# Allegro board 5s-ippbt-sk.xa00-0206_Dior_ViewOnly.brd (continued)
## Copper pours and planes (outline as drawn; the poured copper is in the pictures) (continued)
GND on BOTTOM (solid shape): 22.57,4.89 22.57,4.5 22.95,4.12 23.97,4.12 24.6,4.76 25.37,4.76 25.49,4.63 25.49,2.47 25.24,2.22 17.29,2.22 15.74,3.77 15.74,5.17 15.84,5.27 22.19,5.27
GND on BOTTOM (solid shape): 115.03,38.67 115.03,36.25 114.9,36.13 114.62,36.13 113.61,37.14 109.44,37.14 109.31,37.27 109.31,38.77 109.83,39.29 112.73,39.29 112.74,39.3 114.39,39.3
GND on BOTTOM (solid shape): 113.25,30.67 113.25,27.24 111.5,25.49 107.54,25.49 107.26,25.76 107.26,28.63 107.27,28.65 107.27,29.13 107.28,29.14 107.28,31.81 107.41,31.94 111.98,31.94
GND on BOTTOM (solid shape): 46.04,87.93 54.99,87.93 56.1,86.82 56.1,82.21 54.6,80.71 53.1,80.71 51.6,79.21 51.6,75.19 49,72.59 49,69.12 49.04,69.08 49.04,67.47 47.07,65.49 42.65,65.49 41.35,66.8 41.35,89.98 41.67,90.29 43.68,90.29
GND on BOTTOM (solid shape): 84.93,47.09 84.93,46.04 84.17,45.27 82.77,45.27 82.16,45.88 82.16,46.59 82.39,46.82 82.98,46.82 83.03,46.87 83.04,46.88 83.17,46.95 83.24,47.08 83.25,47.09 83.64,47.48 83.65,47.48 83.77,47.56 83.85,47.68 83.85,47.69 83.95,47.79 84.23,47.79
GND on BOTTOM (solid shape): 32.86,20.51 32.86,19.62 32.73,19.49 31.97,19.49 31.84,19.62 31.84,20.05 31.86,20.08 31.89,20.1 32.2,20.28 32.26,20.63 32.27,20.72 32.35,20.76 32.61,20.76
GND on BOTTOM (solid shape): 41.78,14.59 42.35,14.59 42.91,15.15 43.18,15.15 43.25,15.11 43.28,15.03 43.44,14.66 43.84,14.61 43.87,14.62 44.06,14.44 44.06,10.47 43.71,10.12 41.37,10.12 41.01,10.47 41.01,15.05 41.11,15.15 41.22,15.15
GND on BOTTOM (solid shape): 58.73,47.75 58.73,47.75 58.76,47.65 58.82,47.56 58.82,47.56 58.92,47.47 59.02,47.47 59.33,47.16 59.33,46.93 59.62,46.64 59.62,46.22 59.62,46.13 59.46,45.97 57.71,45.97 57.65,46.03 57.65,46.45 57.82,46.61 58.17,46.77 58.23,47.15 58.23,47.61 58.47,47.85 58.63,47.85
GND on BOTTOM (solid shape): 59.69,70.33 59.69,70.26 59.68,70.25 59.68,70.18 59.46,69.96 59.46,69.93 59.45,69.91 59.36,69.78 59.34,69.63 59.1,69.39 58.85,69.31 58.73,69.09 58.72,69.05 58.68,69.04 58.42,69.04 58.33,69.12 58.33,69.63 58.29,69.67 58.29,69.71 58.06,69.93 58.06,70.61 58.28,70.83 59.19,70.83
GND on BOTTOM (solid shape): 78.93,53.36 79.01,53.33 79.11,53.27 79.24,53.24 79.3,53.2 79.33,53.12 79.37,52.93 79.53,52.8 79.56,52.79 79.56,52.44 79.49,52.37 79.49,52.37 79.41,52.32 79.36,52.24 79.36,52.24 79.16,52.04 79.04,52.04 78.36,51.36 78.01,51.36 77.55,51.83 77.55,52.35 78.03,52.84 78.07,52.82 78.36,52.83 78.51,53.08 78.54,53.14 78.6,53.18 78.75,53.22 78.86,53.32
GND on BOTTOM (solid shape): 30.04,52.76 30.04,39.67 28.85,38.49 27.43,38.49 26.09,39.83 24.36,39.83 23.67,39.15 22.6,39.15 22.4,39.35 22.4,39.73 22.14,39.99 16.78,39.99 15.44,41.33 15.44,46.44 16.99,47.99 23.57,47.99 23.8,48.22 25.11,48.22 25.12,48.15 25.13,48.09 25.15,48.03 25.18,47.97 25.21,47.91 25.25,47.86 25.3,47.81 25.35,47.77 25.41,47.74 25.47,47.71 25.53,47.7 25.6,47.69 25.66,47.68 25.73,47.69 25.79,47.7 25.85,47.73 25.91,47.76 25.97,47.79 26.02,47.83 26.06,47.88 26.1,47.94 26.13,47.99 26.16,48.06 26.17,48.12 26.18,48.19 26.18,48.25 26.17,48.32 26.16,48.38 26.13,48.44 26.1,48.5 26.06,48.55 26.02,48.6 25.97,48.65 25.91,48.68 25.85,48.71 25.79,48.73 25.73,48.75 25.66,48.75 25.6,48.75 25.53,48.74 25.47,48.72 25.41,48.7 25.35,48.66 25.3,48.62 25.25,48.58 25.21,48.53 25.18,48.47 25.15,48.41 25.13,48.35 25.12,48.28 25.11,48.22 23.8,48.22 24.6,49.01 24.6,52.48 25.07,52.96 29.84,52.96
GND on BOTTOM (solid shape): 71.91,56.87 71.91,56.79 71.59,56.46 71.39,56.36 71.28,56.17 71.04,55.93 70.77,55.93 70.76,55.94 70.63,56.02 70.49,56.03 70.03,56.03 69.91,56.15 69.9,56.16 69.9,56.16 69.62,56.44 69.62,56.49 69.65,56.54 69.7,56.58 69.75,56.65 69.78,56.72 69.93,56.87 70,56.97 70.17,57.06 70.34,56.97 70.41,56.87 70.53,56.75 70.55,56.69 70.57,56.67 70.75,56.51 70.99,56.47 71.04,56.47 71.06,56.49 71.07,56.5 71.21,56.59 71.3,56.72 71.31,56.74 71.32,56.82 71.37,56.87 71.44,56.87 71.61,57.07 71.71,57.07
GND on BOTTOM (solid shape): outline of 110 points within 27.78,8.82 32.73,14.41
GND on BOTTOM (solid shape): 60.34,65.71 60.34,65.62 60.19,65.49 60.12,65.3 60.1,65.21 60.1,65.11 60.1,65.1 60.09,65.05 60.06,65.04 59.86,64.73 60.1,64.45 60.14,64.43 60.17,64.38 60.12,64.27 60.11,64.15 60.01,64.04 59.93,63.96 59.9,63.92 59.86,63.9 59.82,63.92 59.61,64.06 59.37,63.99 59.36,63.97 59.21,63.97 58.92,63.68 58.91,63.68 58.83,63.68 58.71,63.81 58.71,64.04 58.72,64.05 58.8,64.18 58.8,64.32 58.82,64.41 58.89,64.45 59.11,64.58 59.15,64.83 59.14,64.85 59.22,64.94 59.46,65.05 59.51,65.3 59.53,65.38 59.6,65.42 59.8,65.53 59.86,65.75 59.86,65.77 59.88,65.81 60.01,65.84 60.13,65.92
GND on BOTTOM (solid shape): 73.39,47.05 73.44,46.98 73.45,46.9 73.49,46.82 73.53,46.78 73.6,46.72 73.79,46.53 73.79,45.77 73.6,45.58 73.25,45.58 72.65,44.99 70.72,44.99 70.37,45.34 70.37,46.29 70.54,46.38 70.61,46.57 70.61,46.69 70.62,46.73 70.64,46.73 70.98,46.73 71.13,47.04 71.18,47.07 71.23,47.07 71.3,47.06 71.37,47.07 71.42,47.07 71.47,47.04 71.62,46.73 71.96,46.73 71.98,46.73 71.99,46.69 71.99,46.57 72.27,46.29 72.55,46.57 72.55,46.69 72.56,46.73 72.58,46.73 72.93,46.73 73.07,47.04 73.12,47.07 73.17,47.07 73.24,47.06 73.31,47.07
GND on BOTTOM (solid shape): 85.54,70.93 85.54,68.23 84.9,67.59 84.54,67.59 84.45,67.64 84.44,67.74 84.16,68.23 83.76,67.82 83.64,67.7 83.35,67.7 83.3,67.75 83.25,67.8 83.23,67.81 83.22,67.87 83.22,67.88 83.25,67.97 83.24,68.06 83.36,68.18 83.78,68.26 83.77,68.68 83.74,68.76 83.77,68.82 83.8,69.27 83.36,69.34 83.32,69.31 83.19,69.45 83.21,69.48 83.14,69.92 82.7,69.9 82.63,69.87 82.56,69.89 82.38,69.98 82.19,69.95 82.08,70.06 81.93,70.1 81.81,70.1 81.79,70.09 81.75,70.09 81.71,70.09 81.68,70.1 81.58,70.1 81.58,70.29 82.08,70.79 83.95,70.79 83.95,70.8 84.52,71.36 85.1,71.36
GND on BOTTOM (solid shape): 83,66.27 83,66.08 82.91,65.98 82.9,65.98 82.78,65.87 82.74,65.72 82.74,65.48 82.32,65.06 82.32,65.05 82.22,64.97 82.18,64.92 82.1,64.88 82.02,64.92 81.79,65.06 81.55,64.97 81.54,64.96 81.28,64.96 81.26,64.97 81.01,65.05 80.78,64.9 80.7,64.85 80.61,64.9 80.54,64.98 80.44,65.04 80.39,65.09 80.39,65.17 80.41,65.42 80.29,65.63 80.24,65.67 80.2,65.71 80.18,65.75 80.19,65.8 80.27,65.85 80.34,65.91 80.35,65.93 80.59,65.93 80.75,65.77 80.96,65.45 81.32,65.59 81.41,65.65 81.49,65.6 81.82,65.44 82.07,65.71 82.08,65.75 82.12,65.77 82.39,65.93 82.46,66.25 82.64,66.43 82.84,66.43
GND on BOTTOM (solid shape): 76.91,50.25 76.96,50.3 77.03,50.31 77.15,50.29 77.28,50.31 77.31,50.31 77.34,50.28 77.39,50.19 77.48,50.12 77.53,50.03 77.48,49.94 77.47,49.93 77.32,49.67 77.48,49.41 77.53,49.32 77.48,49.23 77.45,49.21 77.35,49.1 77.32,48.97 77.33,48.88 77.35,48.84 77.37,48.8 77.39,48.76 77.42,48.69 77.39,48.63 77.15,48.39 76.92,48.36 76.75,48.2 76.73,48.18 76.48,48.18 76.47,48.19 76.38,48.26 76.28,48.3 76.19,48.32 75.99,48.31 75.95,48.45 75.85,48.55 75.8,48.63 75.84,48.71 75.92,48.79 75.96,48.9 76,48.92 76.02,48.91 76.12,48.9 76.23,48.91 76.3,48.91 76.35,48.85 76.84,48.73 76.78,49.23 76.73,49.32 76.78,49.41 76.94,49.67 76.78,49.94 76.73,50.03 76.88,50.2 76.9,50.23
GND on BOTTOM (solid shape): 79.73,69.3 80,69.15 80.26,69.3 80.35,69.3 80.55,69.1 80.55,69.08 80.58,69.01 80.62,68.94 80.7,68.87 80.8,68.83 80.82,68.83 81.22,68.43 81.69,67.95 81.81,67.95 82.38,67.37 82.38,67.09 82.29,67 82,67 81.99,67 81.85,67.04 81.71,67 81.7,67 81.29,67 81.27,67 81.12,67.04 80.97,66.99 80.91,66.94 80.87,66.88 80.78,66.83 80.69,66.88 80.45,67.04 80.19,66.93 80.15,66.86 79.75,66.86 79.68,66.89 79.62,66.9 79.6,66.9 79.51,66.99 79.5,67.02 79.5,67.26 79.58,67.38 79.61,67.52 79.61,67.53 79.63,67.57 79.76,67.62 79.81,67.61 79.85,67.59 80.3,67.47 80.56,67.86 80.54,67.99 80.46,68.12 80.44,68.18 80.46,68.25 80.44,68.8 79.88,68.82 79.85,68.8 79.82,68.82 79.58,68.9 79.36,68.78 79.31,68.78 79.2,68.67 79.17,68.67 78.94,68.6 78.79,68.42 78.78,68.39 78.52,68.39 78.46,68.45 78.46,68.74 78.56,68.84 78.75,68.84 79.11,69.2 79.12,69.21 79.21,69.24 79.29,69.3
GND on BOTTOM (solid shape): outline of 248 points within 5.5,4.95 13.5,12.95
GND on BOTTOM (solid shape): outline of 248 points within 5.5,110.95 13.5,118.95
GND on BOTTOM (solid shape): outline of 248 points within 110.5,110.95 118.5,118.95
GND on BOTTOM (solid shape): outline of 248 points within 110.5,4.95 118.5,12.95
GND on BOTTOM (solid shape): outline of 115 points within 75.97,64.85 79.53,69.3
GND on BOTTOM (solid shape): outline of 142 points within 72.5,61.83 75.56,68.91
GND on BOTTOM (solid shape): outline of 2749 points within 73.96,53.11 85.01,65.8
GND on BOTTOM (solid shape): outline of 4388 points within 0.51,0.51 123.49,121.99
GND on BOTTOM (solid shape): outline of 5719 points within 57.62,45.68 75.89,73.11
GND on VCC (solid shape): outline of 3194 points within 0.51,0.51 123.49,122.79
GND on IN1 (solid shape): outline of 1232 points within 13.56,103.31 28.29,120.7
GND on IN1 (solid shape): outline of 325 points within 0.51,0.51 123.49,121.99
GND on IN2 (solid shape): outline of 324 points within 0.51,0.51 123.49,121.99
GND on GND (solid shape): outline of 3194 points within 0.51,0.51 123.49,122.79
+1P0V on TOP (solid shape): outline of 345 points within 56.33,34.13 69.13,40.19
+1P0VSB on BOTTOM (solid shape): 75.44,61.77 75.52,61.8 75.59,61.76 75.84,61.64 76.1,61.76 76.17,61.8 76.25,61.77 76.38,61.63 76.38,61.46 76.26,61.34 76.18,61.31 76.11,61.35 75.78,61.48 75.54,61.22 75.52,61.19 75.48,61.17 75.47,61.17 75.31,61.14 75.18,61.05 75.15,61.02 75.1,61.05 75.06,61.06 75.01,61.09 74.98,61.14 74.96,61.21 74.82,61.35 74.71,61.35 74.63,61.37 74.56,61.41 74.48,61.49 74.4,61.49 74.4,61.63 74.49,61.63 74.49,61.63 75.3,61.63
+1P0VSB on BOTTOM (solid shape): 81.65,69.9 81.75,69.88 81.84,69.9 81.93,69.9 82.01,69.85 82.03,69.76 82.15,69.37 82.56,69.4 82.57,69.41 82.72,69.41 82.73,69.4 82.86,69.34 83.01,69.34 83.17,69.18 83.17,69.03 82.88,68.74 82.79,68.71 82.72,68.75 82.31,68.85 82.19,68.45 82.19,68.42 82.17,68.39 82.11,68.32 82.06,68.24 82.05,68.24 82.02,68.21 81.84,68.21 81.65,68.4 81.65,68.47 81.66,68.48 81.72,68.68 81.64,68.87 81.77,69.29 81.45,69.58 81.46,69.63 81.46,69.67 81.58,69.8 81.58,69.85 81.63,69.9
+1P05V on TOP (solid shape): 66.24,39.84 66.24,38.52 66.06,38.34 65.5,38.34 65.24,38.59 65.24,39.84 65.35,39.94 66.13,39.94
+1P5V on BOTTOM (solid shape): 36.29,21.4 36.29,19.62 36.16,19.49 35.91,19.49 35.65,19.74 34.26,19.74 34.13,19.87 34.13,20.76 33.62,21.27 33.49,21.27 33.37,21.4 33.37,21.78 35.91,21.78
+1P05V on BOTTOM (solid shape): 66.39,39.07 66.39,38.72 67.3,37.8 67.68,37.8 67.94,37.55 67.96,37.55 68.14,37.37 68.15,37.37 68.28,37.29 68.43,37.27 68.58,37.3 68.7,37.37 69.31,37.37 69.5,37.18 69.5,34.24 69.26,33.99 68.52,33.99 68.22,34.3 66.72,34.3 66.59,34.43 66.59,34.83 66.69,34.93 67.86,34.93 68.29,35.37 68.29,36.23 68.14,36.38 66.92,36.38 65.4,37.91 65.4,39.1 65.65,39.35 66.11,39.35
+1P05V on BOTTOM (solid shape): outline of 114 points within 67.31,57.1 68.93,62.91
+1P05V on IN1 (solid shape): 67.96,62.59 68.14,62.42 68.14,62.06 68.1,61.98 68.01,61.96 67.49,61.57 68.01,61.18 68.1,61.16 68.14,61.08 68.14,59.93 67.83,59.62 67.76,59.61 67.24,59.61 66.88,59.96 66.88,62.11 67.37,62.59 67.96,62.59
+1P35V on TOP (solid shape): 62.12,44.21 62.12,41.84 61.99,41.72 59.02,41.72 58.89,41.84 58.89,44.13 59.02,44.26 62.07,44.26
+1P35V on BOTTOM (solid shape): 62.12,43.27 62.12,38.29 61.99,38.16 59.96,38.16 59.45,38.67 57.17,38.67 56.79,39.05 56.79,39.91 57.1,40.23 58.06,40.23 58.65,40.16 58.68,40.75 58.67,40.79 58.68,40.82 58.77,40.97 58.79,41.13 58.79,43.38 58.89,43.48 61.9,43.48
+1P35V on IN2 (solid shape): outline of 1417 points within 57.83,41.33 69.57,61.93
+1P35V_DUAL on TOP (solid shape): outline of 9156 points within 21.56,33.18 66.7,89.37
+1P35V_DUAL on BOTTOM (solid shape): 55.34,41.59 55.34,40.32 55.21,40.19 54.2,40.19 54.14,40.24 54.15,40.27 54.16,40.48 54.07,40.67 54.07,41.46 54.58,41.97 54.96,41.97
+1P35V_DUAL on BOTTOM (solid shape): 22.45,77.78 22.45,76.89 21.61,76.05 15.26,76.05 14.39,76.92 13.8,76.92 13.78,76.95 13.78,77.07 13.81,77.1 14.23,77.1 14.25,77.08 15.4,77.08 15.44,77.05 17.11,77.05 18.1,78.04 22.19,78.04
+1P35V_DUAL_BOOT_C on BOTTOM (solid shape): 16.83,77.81 16.83,77.38 16.75,77.29 15.4,77.29 15.39,77.3 14.28,77.3 14.26,77.31 13.8,77.31 13.78,77.33 13.78,77.48 13.8,77.5 14.31,77.5 14.34,77.53 15.04,77.53 15.45,77.94 16.71,77.94
+1P35V_DUAL_HG_D on TOP (solid shape): 16.73,81.21 16.73,79.82 16.6,79.69 15.71,79.69 15.46,79.94 15.46,80.32 15.08,80.7 14.44,80.7 14.32,80.83 14.32,81.21 14.44,81.34 16.6,81.34
+1P35V_DUAL_HG_D on BOTTOM (solid shape): 15.13,78.47 15.13,78.04 14.83,77.73 14.24,77.73 14.22,77.71 13.8,77.71 13.78,77.73 13.78,77.86 13.8,77.89 14.24,77.89 14.45,78.1 14.45,78.4 14.7,78.65 14.95,78.65
+1P35V_DUAL_LG_D on TOP (solid shape): 14.7,91.75 14.7,91.37 14.57,91.25 11.87,91.25 11.78,91.33 11.78,91.75 11.9,91.88 14.57,91.88
+1P35V_DUAL_PHASE_D on TOP (solid shape): 20.29,88.96 20.29,82.86 19.23,81.81 17,81.81 16.78,81.59 14.57,81.59 14.32,81.85 14.32,83.37 14.95,84.01 14.95,88.06 15,88.11 15,89.25 14.95,89.3 14.95,91.37 15.21,91.63 17.62,91.63
+1P35V_DUAL_SN_C on TOP (solid shape): 14.09,85.63 14.09,84.39 13.71,84.01 12.67,84.01 12.54,84.13 12.54,86.29 12.67,86.42 13.3,86.42
+1P35V_DUAL_VIN on TOP (solid shape): 12.67,83.12 12.94,83.12 13.17,83.04 13.41,83.12 13.81,83.12 13.94,82.99 13.94,80.83 9.75,80.83 7.71,82.86 7.71,85.4 7.97,85.66 10.13,85.66
+1P35V_DUAL_VIN on BOTTOM (solid shape): 11.78,84.01 11.78,82.99 11.65,82.86 9.44,82.86 8.81,82.23 8.22,82.23 7.89,82.56 6.65,82.56 6.44,82.76 6.44,85.53 6.57,85.66 10.13,85.66
+3P3V on TOP (solid shape): 31.34,22.54 31.34,19.11 32.1,18.35 33.42,18.35 34.17,17.6 34.17,16.1 34,15.93 30.7,15.93 29.43,17.2 29.43,22.54 29.94,23.05 30.83,23.05
+3P3V on TOP (solid shape): 85.87,8.72 85.87,7.88 85.51,7.53 83.53,7.53 83.3,7.3 83.3,6.82 83.18,6.69 82.54,6.69 82.35,6.88 82.35,8.38 83.13,9.15 83.76,9.15 83.81,9.2 85.39,9.2
+3P3V on TOP (solid shape): 115.13,37.58 115.13,37.32 115.08,37.27 113.58,37.27 113.56,37.25 113.56,37.09 113.58,37.07 115.08,37.07 115.13,37.02 115.13,36.81 115.08,36.76 113.5,36.76 112.97,36.23 111.45,36.23 111.14,36.53 111.14,37.58 111.27,37.7 115,37.7
+3P3V on TOP (solid shape): 115.13,20.48 115.13,20.3 115.11,20.28 113.61,20.28 113.58,20.25 113.58,20.08 113.61,20.05 115.11,20.05 115.13,20.02 115.13,19.8 115.11,19.77 113.61,19.77 113.58,19.74 113.58,19.59 113.61,19.57 115.08,19.57 115.13,19.52 115.13,19.31 115.08,19.26 113.52,19.26 113.48,19.26 113,19.26 112.98,19.25 111.1,19.25 110.58,18.73 110.58,16.32 110.6,16.3 110.3,16.01 108.88,16.01 108.45,16.44 108.45,17.69 108.84,18.08 108.84,19.28 110.1,20.53 115.08,20.53
+3P3V on BOTTOM (solid shape): 31.46,22.28 31.46,19.87 31.34,19.74 29.94,19.74 29.81,19.87 29.81,22.28 30.19,22.67 31.08,22.67
+3P3V on BOTTOM (solid shape): 110.71,19.69 110.71,15.93 110.46,15.68 108.55,15.68 108.3,15.93 108.3,17.54 108.91,18.14 108.91,19.8 109.24,20.13 110.28,20.13
+3P3V on BOTTOM (solid shape): 6.81,67.4 6.81,66.88 6.4,66.47 5.09,66.47 4.46,65.84 4.46,62.86 4.11,62.51 3.52,62.51 3.17,62.86 3.17,67.07 3.84,67.74 6.47,67.74
+3P3V on BOTTOM (solid shape): outline of 454 points within 82.26,4.28 94.94,11.06
+3P3V on IN1 (solid shape): 83.43,8.7 83.43,7.15 83.08,6.79 82.03,6.79 81.55,7.27 81.55,9.48 82.64,9.48
+3P3V on IN1 (solid shape): 95.83,9.15 95.83,8.19 95.39,7.76 94.35,7.76 94,8.11 94,9.74 95.24,9.74
+3P3V on IN1 (solid shape): 35.91,16.57 35.91,15.17 35.65,14.92 31.34,14.92 31.21,15.05 31.21,16.57 31.46,16.82 35.65,16.82
+3P3V on IN1 (solid shape): 110.72,17.55 110.72,16.07 110.48,15.83 107.21,15.83 106.37,16.67 106.37,17.28 107.05,17.97 110.3,17.97
+3P3VSB on TOP (solid shape): 21.8,96.53 21.8,94.42 21.65,94.27 19.54,94.27 19.18,94.62 19.18,96.5 19.69,97.01 21.32,97.01
+3P3VSB on TOP (solid shape): 45.59,93.71 45.59,92.8 45.08,92.29 43.86,92.29 43.27,92.87 43.27,94.78 43.5,95.01 44.29,95.01
+3P3VSB on TOP (solid shape): 62.76,95.08 62.76,94.62 62.31,94.17 62.31,93.38 62.13,93.2 60.45,93.2 59.94,92.69 58.41,92.69 58.21,92.89 58.21,94.19 58.29,94.26 59.7,94.26 60.67,95.24 62.6,95.24
+3P3VSB on TOP (solid shape): outline of 193 points within 30.8,91.22 36.06,94.42
+3P3VSB on BOTTOM (solid shape): 25.67,12.25 25.67,11.36 25.21,10.91 23.28,10.91 23.08,11.11 23.08,12.43 23.31,12.66 25.27,12.66
+3P3VSB on BOTTOM (solid shape): outline of 226 points within 29.15,2.98 40.61,19.36
+3P3VSB on IN1 (solid shape): 5.94,71.57 5.94,68.85 5.81,68.72 4.05,68.72 3.85,68.91 3.85,71.51 4.2,71.86 5.65,71.86
+3P3VSB on IN1 (solid shape): 7.24,92.04 7.24,89.32 7.1,89.19 5.34,89.19 5.14,89.39 5.14,91.98 5.5,92.34 6.95,92.34
+3P3VSB on IN2 (solid shape): 5.91,71.41 5.91,69.5 5.63,69.22 4.11,69.22 3.8,69.53 3.8,71.28 4.23,71.71 5.61,71.71
+3P3VSB on IN2 (solid shape): 7.51,93.1 7.51,91.55 7.21,91.25 5.3,91.25 5.02,91.53 5.02,93.05 5.33,93.35 7.26,93.35
+3P3VSB on IN2 (solid shape): 21.58,96.45 21.58,94.9 21.28,94.6 19.37,94.6 19.09,94.88 19.09,96.4 19.4,96.71 21.33,96.71
+3P3VSB on IN2 (solid shape): 24.35,11.87 24.35,10.47 23.61,9.74 22.65,9.74 22.19,10.19 22.19,12.12 22.45,12.38 23.84,12.38
+3P3VSB on IN2 (solid shape): 62.83,95.03 62.83,94.47 61.26,92.9 59.45,92.9 59.05,93.3 59.05,93.91 60.47,95.34 62.53,95.34
+3P3VSB on IN2 (solid shape): outline of 398 points within 44.49,91.55 55.24,97.21
+3P3VSB_HG_D on BOTTOM (solid shape): 29.1,10.9 29.1,10.51 29.02,10.43 27.35,10.43 27.18,10.25 27.18,9.87 27.01,9.71 26.64,9.71 26.51,9.84 26.51,10.07 25.93,10.65 25.93,11.23 25.94,11.25 28.75,11.25
+3P3VSB_LG_D on BOTTOM (solid shape): 25.49,1.71 25.49,1.46 25.37,1.33 22.19,1.33 22.06,1.46 22.06,1.71 22.19,1.84 25.37,1.84
+3P3VSB_LG_D on BOTTOM (solid shape): 12.06,31.16 11.78,30.87 11.3,30.87 11.19,30.97 11.19,31.84 11.5,32.14 12.06,32.14
+3P3VSB_PHASE_D on BOTTOM (solid shape): 28.92,10.01 28.92,8.82 30.57,7.17 30.57,1.84 30.19,1.46 26,1.46 25.84,1.62 25.84,7.13 26.51,7.81 26.51,9.08 26.76,9.33 27.03,9.33 27.54,9.84 27.54,10 27.62,10.08 28.85,10.08
+3P3VSB_SN_D on BOTTOM (solid shape): 23.84,6.92 23.84,4.5 23.72,4.38 23.08,4.38 22.95,4.5 22.95,5.14 22.12,5.98 22.12,6.33 22.32,6.54 22.57,6.54 23.08,7.04 23.72,7.04
+V_AXG_HG_D on BOTTOM (solid shape): 103.09,37.78 103.09,36.89 102.96,36.76 99.79,36.76 99.66,36.89 99.66,37.65 100.17,38.16 102.71,38.16
+V_AXG_HG_D on BOTTOM (solid shape): 103.19,57.97 103.19,57.69 102.96,57.46 102.63,57.46 102.11,57.99 102.11,58.46 102.71,58.46
+V_AXG_LGATE_D on BOTTOM (solid shape): 111.68,25.18 111.68,23.73 111.45,23.5 111.02,23.5 110.29,24.23 109.28,24.23 109.19,24.32 107.41,24.32 107.28,24.44 107.28,24.95 107.41,25.08 108.81,25.08 108.96,25.23 111.63,25.23
+V_AXG_PHASE on BOTTOM (solid shape): 101.44,36.25 103.22,36.25 103.47,36 103.47,30.92 104.61,29.78 105.91,29.78 106.67,30.54 106.9,30.54 107.03,30.41 107.03,29.65 106.39,29.02 106.39,24.67 105.83,24.11 96.18,24.11 95.85,24.44 95.85,27.11 95.98,27.24 98.19,27.24 98.43,27.48 98.43,28.8 99.6,29.97 99.6,36.32 99.66,36.38 101.31,36.38
+V_AXG_SN on BOTTOM (solid shape): 106.77,30.95 105.99,30.16 104.87,30.16 104.74,30.29 104.74,31.68 104.87,31.81 106.77,31.81
+VCORE on TOP (solid shape): outline of 458 points within 68.5,58.95 97.22,87.18
+VCORE on BOTTOM (solid shape): outline of 118 points within 71.72,79.13 97.76,85.91
+VCORE on BOTTOM (solid shape): outline of 145 points within 69.6,56.68 72.64,64.27
+VCORE on IN1 (solid shape): outline of 1497 points within 64.48,56.66 74.34,82.71
+VCORE on IN2 (solid shape): outline of 2546 points within 66.92,56.64 77.16,85.38
+VCORE_+19V on BOTTOM (solid shape): 116.55,97.67 116.55,92.92 116.54,92.91 116.54,92.25 115.92,91.63 108.04,91.63 107.31,90.89 107.31,90 107.03,89.72 103.42,89.72 102.86,90.28 102.86,93.46 104.06,94.65 111.69,94.65 111.69,94.65 111.86,94.65 112.11,94.9 112.11,97.59 112.49,97.98 116.25,97.98
+VCORE_HG_D on BOTTOM (solid shape): 101.82,93.91 101.82,93.4 101.69,93.28 98.39,93.28 98.26,93.4 98.26,94.67 98.39,94.8 100.93,94.8
+VCORE_LGATE_D on BOTTOM (solid shape): 109.69,81.59 109.69,80.2 109.44,79.94 106.77,79.94 106.16,80.55 106.16,81.49 106.27,81.59 108.02,81.59 108.17,81.75 109.54,81.75
+VCORE_PHASE on BOTTOM (solid shape): 102.07,92.77 102.07,89.72 102.58,89.21 105.25,89.21 105.76,88.71 105.76,87.94 105.63,87.82 105.5,87.82 105.38,87.94 105.38,88.2 105,88.58 102.96,88.58 102.74,88.35 102.74,87.44 102.74,87.39 102.74,86.57 103.12,86.19 105.66,86.19 105.76,86.09 105.76,85.51 105.58,85.33 105.58,81.11 105.22,80.76 100.65,80.76 100.47,80.93 100.47,84.01 98.01,86.47 95.47,86.47 94.99,86.95 94.99,89.09 95.37,89.47 97.12,89.47 98.52,90.86 98.52,92.82 98.65,92.95 101.9,92.95
+VCORE_SN on BOTTOM (solid shape): 105.02,87.26 105.63,87.26 105.68,87.21 105.68,86.62 105.55,86.5 103.47,86.5 102.99,86.98 102.99,87.89 103.29,88.2 104.08,88.2
+VNN on TOP (solid shape): 73.4,60.99 73.4,59.98 73.52,59.86 73.52,56.05 72.55,55.08 69.29,55.08 69.07,55.3 69.07,56.12 69.33,56.38 71.81,56.38 71.94,56.51 72.07,56.51 72.23,56.67 72.23,57.16 72.07,57.32 71.78,57.32 71.49,57.62 71.5,57.72 71.64,57.9 71.67,58.02 71.97,58.14 72.09,58.45 72.23,58.6 72.71,58.6 72.81,58.71 72.81,59.67 72.75,59.73 72.6,59.73 72.58,59.75 72.41,59.75 72.25,59.91 72.25,60.91 72.43,61.1 73.3,61.1
+VNN on TOP (solid shape): outline of 487 points within 72.23,28.38 99.37,40.04
+VNN on BOTTOM (solid shape): 77.39,36.94 79.16,36.94 79.47,36.64 79.47,35.37 79.15,35.05 79,34.95 78.9,34.79 78.71,34.6 78.71,33.33 78.52,33.14 72.8,33.14 72.74,33.21 72.74,37.52 72.99,37.78 76.55,37.78
+VNN on BOTTOM (solid shape): 98.58,39.49 99.27,39.49 99.51,39.25 99.51,38.06 99.1,37.65 99.1,30.92 98.7,30.51 94.43,30.51 94,30.95 93.36,30.95 92.8,31.51 92.8,33.21 91.91,34.1 90.77,34.1 90.48,34.39 90.48,36.59 91.33,37.44 91.33,38.08 92.75,39.51 98.57,39.51
+VNN on BOTTOM (solid shape): outline of 127 points within 68.87,54.71 73.8,60.56
+VNN on IN1 (solid shape): outline of 2457 points within 65.63,36.06 79.39,60.22
+VNN on IN2 (solid shape): outline of 3510 points within 65.27,31.56 78.61,60.26
+VNN_+19V on BOTTOM (solid shape): 109.03,37.25 109.03,36.43 109.36,36.1 109.44,36.1 109.54,36 114.24,36 114.85,35.39 114.85,31.81 114.39,31.35 113.86,31.35 112.67,32.55 104.44,32.55 104.01,32.98 104.01,37.32 104.36,37.68 108.6,37.68
+VTT_DDR on TOP (solid shape): 36.67,31.02 38.3,31.02 38.46,30.86 38.46,30.2 38.37,30.11 35.4,30.11 34.66,29.37 33.62,29.37 32.81,30.18 30.62,30.18 30.29,30.51 30.29,31.58 30.4,31.68 36.01,31.68
+VTT_DDR on BOTTOM (solid shape): 15.59,75.4 15.59,71.56 15.46,71.43 12.84,71.43 12.29,71.99 12.29,72.53 12.39,72.63 13.67,72.63 14.63,73.09 14.47,74.15 14.44,74.17 14.44,74.33 14.57,74.62 14.44,74.92 14.44,74.96 14.44,74.96 14.44,75.11 13.78,75.78 13.78,76.67 13.81,76.69 14.29,76.69
CARD_3V3 on TOP (solid shape): outline of 195 points within 7.56,59.65 11.42,67.42
CARD_3V3 on BOTTOM (solid shape): 9.64,69.2 9.64,65.26 9.44,65.06 7.97,65.06 7.51,65.52 7.51,67.04 5.96,68.59 5.96,69.22 6.47,69.73 9.11,69.73
CARD_3V3 on BOTTOM (solid shape): 9.61,60.95 9.61,60.76 9.52,60.66 9.52,59.95 9.49,59.93 9.49,59.09 9.44,59.04 9.29,59.04 9.24,59.09 9.24,59.75 8.65,60.33 8.65,60.69 9.07,61.11 9.46,61.11
CARD_3V3_F on TOP (solid shape): 14.96,63.64 15.03,63.55 15.13,63.49 15.49,63.13 17.09,63.13 17.29,62.92 17.29,62.26 17.16,62.14 15.28,62.14 14.57,62.85 14.57,63.46 14.75,63.64
CARD_3V3_F on BOTTOM (solid shape): 13.05,69.53 13.05,68.91 12.79,68.65 12.36,68.65 12.36,68.65 11.91,68.46 11.97,67.97 12,67.9 11.96,67.82 11.84,67.37 12.22,67.1 12.3,67.1 12.45,66.95 14.16,66.95 14.66,66.45 14.66,65.9 14.41,65.57 14.5,65.17 14.5,64.13 14.94,63.68 14.94,63.68 15.09,63.51 15.3,63.44 15.32,63.44 15.55,63.22 15.55,62.8 15.38,62.63 14.53,62.63 14.37,62.8 13.51,62.8 13.3,63 13.3,65.08 13.05,65.34 12.69,65.34 12.6,65.38 12.6,65.48 12.22,66.05 11.85,65.48 11.84,65.38 11.76,65.34 10.51,65.34 10.13,65.72 10.13,69.53 10.37,69.77 12.81,69.77
DRAM_V1P0_S0IX on TOP (solid shape): 67.64,42.37 67.64,41.96 67.76,41.84 67.76,40.88 67.66,40.78 66.74,40.78 66.65,40.87 66.65,41.65 66.74,41.74 66.74,42.36 66.72,42.39 66.72,42.49 66.83,42.59 67.42,42.59
DRAM_V1P0_S0IX on TOP (solid shape): 68.14,57.81 68.14,57.48 67.98,57.32 67.62,57.32 67.53,57.23 67.53,53.73 67.43,53.63 66.97,53.63 66.84,53.76 66.84,57.82 66.96,57.94 68.01,57.94
DRAM_V1P0_S0IX on BOTTOM (solid shape): outline of 96 points within 66.58,55.57 67.67,61.33
LAN_REGOUT on BOTTOM (solid shape): 55.62,95.18 57.43,95.18 57.44,95.17 57.56,95.17 57.65,95.08 57.65,93.43 57.6,93.38 56,93.38 54.65,94.73 54.65,95.48 54.72,95.54 55.26,95.54
LAN_REGOUT_R on TOP (solid shape): outline of 178 points within 49.83,93.53 59.78,100.26
LAN_REGOUT_R on BOTTOM (solid shape): 59.66,95.31 59.66,93.28 58.54,92.16 58.31,92.16 58.08,92.39 58.08,92.82 58.18,92.92 58.49,92.92 58.64,93.07 58.64,94.65 58.68,94.65 58.68,94.71 59.4,95.44 59.53,95.44
PCIE_V1P0_S3 on BOTTOM (solid shape): 76.15,55.53 76.29,55.53 76.43,55.38 76.43,55.22 76.24,55.03 76.24,54.28 75.96,54 75.94,53.97 75.91,53.96 74.25,53.96 74.12,54.09 74.12,54.92 74.27,55.06 74.38,55.06 74.51,54.95 74.66,54.89 74.81,54.74 74.87,54.67 74.95,54.61 75.19,54.59 75.37,54.74 75.44,54.81 75.59,54.81 75.91,55.13 75.91,55.48 75.86,55.53 75.84,55.53 75.71,55.66 75.71,55.71 75.79,55.79 75.89,55.79
RING2 on TOP (solid shape): 11.88,105.55 11.88,105.04 12.06,104.86 12.06,104.58 11.77,104.29 11.69,104.23 11.6,104.12 11.17,104.12 10.98,104.31 10.98,104.8 11.27,105.09 11.27,105.44 11.42,105.6 11.83,105.6
RING2 on BOTTOM (solid shape): outline of 184 points within 10.66,103.51 20.21,106.79
RING2_B on TOP (solid shape): 22.42,107.83 22.42,106.33 22.17,106.08 20.74,106.08 19.96,106.87 19.96,107.98 20.08,108.11 22.14,108.11
RING2_B on BOTTOM (solid shape): 22.5,107.48 22.5,106.88 22.61,106.77 23.39,106.77 23.64,106.51 24.03,106.51 24.26,106.39 24.51,106.43 24.54,106.45 24.73,106.26 24.73,105.8 24.65,105.72 23.69,105.72 23.44,105.98 22.17,105.98 22.04,105.85 21.15,105.85 20.92,106.08 20.92,106.82 20.97,106.87 21.46,106.87 21.68,107.1 21.68,107.13 21.69,107.13 21.69,107.49 21.91,107.71 22.27,107.71
SLEEVE on TOP (solid shape): 11.85,106.38 11.85,105.95 11.8,105.9 11.24,105.9 11.02,105.67 11.02,105.19 10.86,105.04 10.51,105.04 10.43,105.11 10.43,106.31 10.61,106.49 11.75,106.49
SLEEVE on BOTTOM (solid shape): outline of 144 points within 6.6,104.43 20.19,109.13
SLEEVE_B on BOTTOM (solid shape): 23.53,111.85 23.54,111.84 23.78,111.43 24.19,111.18 24.21,111.18 24.71,110.68 24.71,109.54 24.53,109.2 24.71,108.87 24.71,107.45 24.66,107.4 24.05,107.4 23.87,107.58 23.76,107.58 23.75,107.58 23.6,107.62 23.45,107.59 23.45,107.59 22.67,107.59 22.35,107.91 21.83,107.91 21.49,107.57 21.49,107.37 21.44,107.32 21,107.32 20.85,107.48 20.85,108.26 20.19,108.92 20.19,109.38 20.85,110.04 20.85,111.46 21.28,111.9 23.49,111.9
UNCORE_V1P0_S0IX on BOTTOM (solid shape): 73.27,61.86 73.27,61.85 73.36,61.72 73.51,61.64 73.98,61.17 73.98,61.02 74.07,60.96 74.13,60.9 74.15,60.83 74.11,60.66 73.95,60.59 73.89,60.58 73.84,60.57 73.8,60.61 73.57,60.7 73.35,60.61 73.22,60.61 72.77,61.06 72.73,61.09 72.71,61.12 72.71,61.25 72.74,61.28 72.77,61.31 72.84,61.62 72.67,61.89 72.65,61.92 72.65,61.96 72.83,62.14 73,62.14
USB_V1P0_S3 on BOTTOM (solid shape): 76.08,63.57 76.19,63.56 76.28,63.5 76.47,63.3 76.47,63.12 76.06,62.71 76.05,62.7 75.95,62.63 75.87,62.52 75.87,62.52 75.72,62.37 75.43,62.37 75.24,62.57 75.05,62.57 74.98,62.64 74.93,62.68 74.93,62.8 75.04,62.91 75.36,62.91 75.79,63.34 75.82,63.34 76.03,63.56
VRP on TOP (solid shape): 8.47,103.21 8.47,102.27 8.57,102.17 9.16,102.17 9.21,102.12 9.21,102.02 9.16,101.96 8.63,101.96 8.59,101.93 8.12,101.93 7.65,102.4 6.55,102.4 6.42,102.52 6.42,103.54 6.52,103.64 8.04,103.64
N17661737 on TOP (solid shape): 62.28,92.67 62.28,92.44 62.13,92.28 61,92.28 60.92,92.29 60.85,92.28 60.61,92.28 60.14,91.81 58.37,91.81 58.27,91.91 58.27,92.32 58.35,92.39 60.1,92.39 60.54,92.84 62.12,92.84
N24358231 on TOP (solid shape): 113,101.66 117.31,101.66 117.7,101.28 117.7,100.14 117.44,99.88 112.74,99.88 112.49,99.63 112.49,99.25 112.36,99.12 111.85,99.12 111.6,99.37 111.6,100.14 111.22,100.52 111.22,102.68 111.35,102.8 111.85,102.8
N24358368 on TOP (solid shape): 119.61,99.92 119.61,99.48 119.47,99.34 118.38,99.34 118.37,99.33 118.22,99.33 116.82,97.93 115.21,97.93 114.91,97.63 113.34,97.63 113,97.29 111.85,97.29 111.78,97.37 111.78,97.77 111.88,97.88 112.77,97.88 113.19,98.29 114.48,98.29 114.85,98.66 116.1,98.66 116.98,99.55 117.65,99.55 118.12,100.03 119.5,100.03
N31476922 on TOP (solid shape): 114.32,99.45 114.32,98.97 114.22,98.87 113.3,98.87 112.69,98.26 111.85,98.26 111.8,98.31 111.8,98.69 111.9,98.79 112.46,98.79 113.23,99.55 114.22,99.55

Small or netless copper shapes (teardrops, artwork), in the pictures only: 800 on TOP, 1482 on BOTTOM, 327 on IN1, 338 on IN2

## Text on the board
